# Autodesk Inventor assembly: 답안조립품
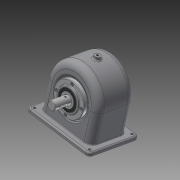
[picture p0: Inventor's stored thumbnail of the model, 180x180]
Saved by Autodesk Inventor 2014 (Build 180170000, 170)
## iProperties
Created: 2016-01
Part Number: 답안조립품
Document SubType Name: Assembly
Designer: Owner
Author: Owner
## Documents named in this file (13)
- C:\Documents and Settings\Owner\바탕 화면\460106V1021\답안조립품.iam
- C:\Documents and Settings\Owner\바탕 화면\460106V1021\1. 본체.ipt
- C:\Documents and Settings\Owner\바탕 화면\460106V1021\뒤커버.ipt
- C:\Documents and Settings\Owner\바탕 화면\460106V1021\볼트 M3 x 8.ipt
- C:\Documents and Settings\Owner\바탕 화면\460106V1021\베어링 6203.ipt
- C:\Documents and Settings\Owner\바탕 화면\460106V1021\축.ipt
- C:\Documents and Settings\Owner\바탕 화면\460106V1021\부시1.ipt
- C:\Documents and Settings\Owner\바탕 화면\460106V1021\키 - 6 x 6 x 22.ipt
- C:\Documents and Settings\Owner\바탕 화면\460106V1021\스퍼기어.ipt
- C:\Documents and Settings\Owner\바탕 화면\460106V1021\앞커버.ipt
- C:\Documents and Settings\Owner\바탕 화면\460106V1021\볼트 M3 x 10.ipt
- C:\Documents and Settings\Owner\바탕 화면\460106V1021\오일씰 28 40 8.ipt
- C:\Documents and Settings\Owner\바탕 화면\460106V1021\부시2.ipt
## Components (9 placed, 3 different names)
1. 1. 본체:1
2. ISO 4762 M3 x 8:1
3. ISO 4762 M3 x 8:2
4. ISO 4762 M3 x 8:3
5. ISO 4762 M3 x 8:4
6. ISO 4762 M3 x 10:1
7. ISO 4762 M3 x 10:2
8. ISO 4762 M3 x 10:3
9. ISO 4762 M3 x 10:4
